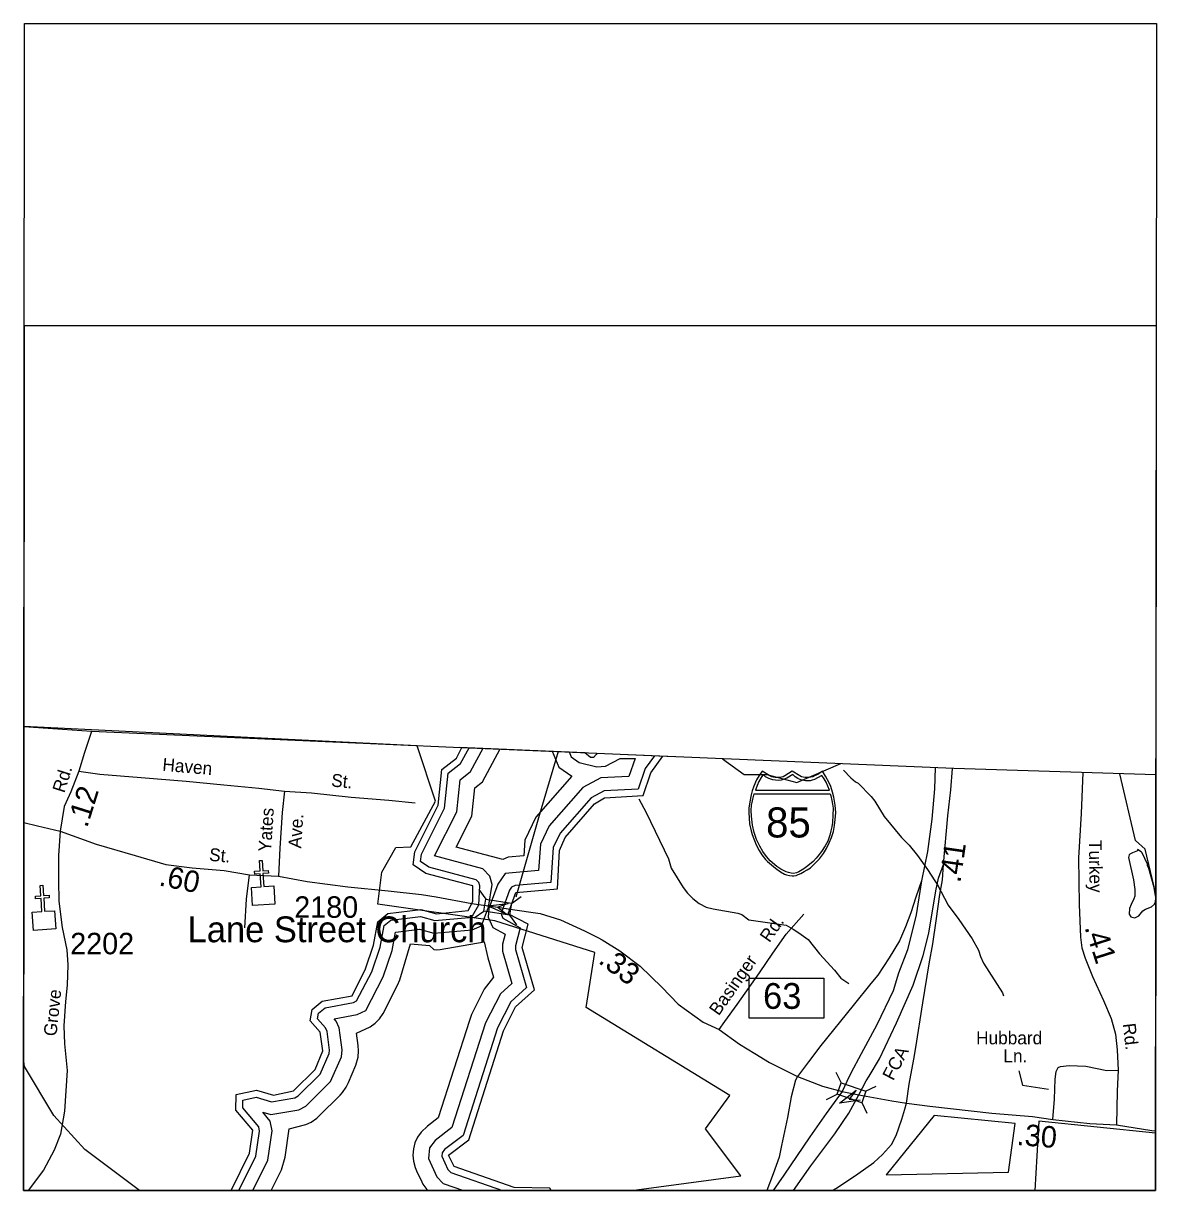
# Model space of a CAD drawing. Extents: x 1513414 to 1532852, y 643392 to 657912.
# Drawn here: x 1513414 to 1520009, y 651120 to 657912 of the extents above; entities that cross this region are included whole.
import ezdxf

# ---------------------------------------------------------------- set-up
doc = ezdxf.new("R2010")
doc.units = 0
doc.layers.add('Default', color=7, linetype='Continuous')

msp = doc.modelspace()

# ---------------------------------------------------------------- linework, layer by layer
at = {"layer": 'Default'}
for p, q in [((1520007.5, 656151.4), (1513418.3, 656151.4)), ((1516681.5, 653667), (1515951, 653698)), ((1517202.2, 653645), (1516751, 653664.1)), ((1516065.3, 652873.3), (1516105.4, 652817.1)), ((1516254.4, 652792), (1516310.5, 652832.1)), ((1516037.6, 652707.4), (1516093.8, 652747.5)), ((1516243, 652723.9), (1516283.1, 652667.8)), ((1518142.8, 651810.5), (1518172.9, 651748.4)), ((1518315.6, 651698.6), (1518377.7, 651728.7)), ((1518087.8, 651651.6), (1518149.8, 651681.7)), ((1518293, 651633.4), (1518323.2, 651571.3))]:
    msp.add_line(p, q, dxfattribs=at)
for points in [[(1513419.9, 657912), (1520009.1, 657912), (1520002.8, 651120.5), (1513413.6, 651120.5)], [(1517888.8, 652951.5), (1517898.3, 652952.5), (1517911.1, 652954.9), (1517923.4, 652959), (1517937.6, 652965.2), (1517958.4, 652976.8), (1517975.1, 652986.6), (1517994.5, 652999.6), (1518020.6, 653023.3), (1518046.6, 653050.7), (1518069.6, 653081.8), (1518087.9, 653110.8), (1518104, 653143.9), (1518117.4, 653174.8), (1518128.1, 653210.2), (1518135.1, 653244.4), (1518138.7, 653280.1), (1518141.1, 653319.7), (1518138.4, 653364.2), (1518130.6, 653409.8), (1518123.4, 653438.1), (1518112.3, 653472.1), (1518103.3, 653493.7), (1518082.5, 653532.2), (1518063.8, 653561.8), (1518036.5, 653542.6), (1518018.8, 653533.2), (1518007.9, 653528.3), (1517996.8, 653526.1), (1517976.3, 653523.6), (1517963.4, 653524.2), (1517951.4, 653526.9), (1517941.3, 653529.1), (1517933.1, 653533.2), (1517888.8, 653561.8), (1517844.6, 653533.2), (1517835.3, 653528.9), (1517825.8, 653526.9), (1517816.6, 653524.4), (1517801.5, 653523.6), (1517789.9, 653524), (1517778.1, 653526.1), (1517768.7, 653528.1), (1517758.2, 653533.2), (1517713, 653561.8), (1517695.3, 653536.1), (1517680.9, 653510.7), (1517665.5, 653474.7), (1517656, 653446.9), (1517649.1, 653424), (1517640.8, 653382.1), (1517636.5, 653345.5), (1517635.7, 653319.7), (1517640.5, 653255.2), (1517647.5, 653220.8), (1517654.7, 653193), (1517678.6, 653133), (1517696.5, 653099.4), (1517712, 653075.2), (1517733.5, 653048), (1517745.2, 653035.1), (1517790, 652995.9), (1517820, 652975.5), (1517843.9, 652962.6), (1517855.1, 652958.3), (1517872.7, 652953.4)], [(1517718.4, 653541), (1517707.4, 653524.1), (1517694.7, 653501.3), (1517684.6, 653477.6), (1517674.2, 653451.4), (1518105.8, 653451.3), (1518095.8, 653473.7), (1518085, 653496.2), (1518073.7, 653516.8), (1518060, 653536.7), (1518035.8, 653521.5), (1518018.2, 653513.1), (1518004, 653508.2), (1517992, 653505.5), (1517973.4, 653504.1), (1517965.1, 653504.6), (1517939.2, 653510.4), (1517921.6, 653517.6), (1517904.9, 653528.7), (1517891.4, 653541.5), (1517857.2, 653520.8), (1517842.1, 653514.1), (1517824.6, 653509.6), (1517805.5, 653507.3), (1517776.1, 653510.4), (1517753, 653518.4), (1517733.2, 653528.7)], [(1518108.4, 653430), (1518113, 653417.8), (1518119.3, 653390.7), (1518122.7, 653369.9), (1518126.1, 653345.9), (1518124.9, 653304.8), (1518122.9, 653262.2), (1518119, 653237), (1518113.8, 653214.1), (1518106.6, 653188.6), (1518095.1, 653154.8), (1518079.2, 653126.1), (1518059.3, 653094.3), (1518037.8, 653066.4), (1518028.5, 653054.9), (1518010.8, 653036.2), (1517978.6, 653010.3), (1517955, 652992.7), (1517926.9, 652976.1), (1517912.6, 652969.7), (1517895.9, 652966.2), (1517882.2, 652967.2), (1517865.6, 652971.6), (1517852.1, 652975.3), (1517822.7, 652991.2), (1517798.8, 653007.1), (1517759.1, 653039.8), (1517737.6, 653064.9), (1517717.6, 653094.3), (1517699.7, 653124.4), (1517680.6, 653164), (1517667.2, 653203.9), (1517657.4, 653247), (1517650.8, 653299.7), (1517650, 653331.7), (1517652, 653362.6), (1517654.9, 653378.7), (1517658.8, 653398.8), (1517666.7, 653429.8)], [(1514740.5, 652884.8), (1514797.3, 652888.7), (1514792.2, 652964.7), (1514760.3, 652962.5), (1514759.3, 652978.5), (1514791.2, 652980.6), (1514787.2, 653040.6), (1514803.2, 653041.7), (1514807.2, 652981.7), (1514839.1, 652983.8), (1514840.2, 652967.9), (1514808.2, 652965.7), (1514813.3, 652889.8), (1514870.8, 652893.5), (1514877.9, 652787.3), (1514747.6, 652778.6)], [(1513464.7, 652740.6), (1513521.5, 652744.5), (1513516.5, 652820.5), (1513484.5, 652818.3), (1513483.5, 652834.3), (1513515.4, 652836.4), (1513511.4, 652896.4), (1513527.4, 652897.5), (1513531.4, 652837.5), (1513563.3, 652839.6), (1513564.4, 652823.7), (1513532.4, 652821.5), (1513537.5, 652745.6), (1513595.1, 652749.3), (1513602.1, 652643.1), (1513471.8, 652634.4)], [(1516105.4, 652817.1), (1516254.5, 652792.3), (1516242.8, 652722.7), (1516093.8, 652747.5)], [(1516226, 652729), (1516114.6, 652778.5), (1516235.8, 652791.3), (1516174.8, 652769)], [(1517637.1, 652356.5), (1518072, 652356.5), (1518072, 652123.3), (1517637.1, 652123.3)], [(1518172.9, 651748.4), (1518315.7, 651698.9), (1518292.6, 651632.2), (1518149.8, 651681.7)], [(1518284.2, 651646.1), (1518163.3, 651630.1), (1518260, 651704.4), (1518219.6, 651653.5)]]:
    msp.add_lwpolyline(points, close=True, dxfattribs=at)
for points in [[(1513418.3, 656151.4), (1513413.6, 651120.5), (1520002.8, 651120.5), (1520007.5, 656151.4)], [(1515706.2, 653709.1), (1513416.1, 653820.9)], [(1515706.2, 653709.1), (1513416.1, 653820.9)], [(1520005, 653539), (1518827.8, 653576.1), (1515916.8, 653699.4), (1513810.1, 653792.1), (1513416.1, 653818.1)], [(1513810.6, 653792.1), (1513769.4, 653670.3), (1513736.4, 653561.3), (1513690.2, 653440.8), (1513650.6, 653354.9), (1513627.8, 653211.3)], [(1515451.4, 652549), (1515476.6, 652685), (1515535.6, 652733), (1515727.6, 652755.4), (1515818.6, 652730.6), (1516002.6, 652749.8), (1516028.6, 652801.9), (1516029.6, 652893.7), (1515755.6, 652964.9), (1515681.6, 653015.7), (1515691.6, 653090.9), (1515828.6, 653363.9), (1515848.6, 653570.3), (1515933.6, 653637.5), (1515965.7, 653699.3)], [(1516951.9, 651120.5), (1517589, 651207.6), (1517383.6, 651479.3), (1517525.8, 651673.5), (1516689.2, 652186.4), (1516739.5, 652507), (1516158.3, 652690.2), (1515476.3, 652786.4), (1515499.2, 652974.2), (1515581.6, 653116.2), (1515668.5, 653120.8), (1515813.1, 653386.6), (1515706.2, 653709.1)], [(1516951.9, 651120.5), (1517589, 651207.6), (1517383.6, 651479.3), (1517525.8, 651673.5), (1516689.2, 652186.4), (1516739.5, 652507), (1516158.3, 652690.2), (1515476.3, 652786.4), (1515499.2, 652974.2), (1515581.6, 653116.2), (1515668.5, 653120.8), (1515813.1, 653386.6), (1515706.2, 653709.1)], [(1515724.5, 653034.8), (1515730.4, 653079), (1515864.4, 653346), (1515886.7, 653549.5), (1515958.4, 653606.1), (1516007.6, 653697.6)], [(1515806.4, 653067.9), (1515935.5, 653325), (1515955.9, 653511.2), (1516015.5, 653558.3), (1516088.7, 653694.4)], [(1515933.3, 653119.7), (1516023.3, 653299), (1516041.4, 653463.8), (1516086.1, 653499.1), (1516188.9, 653690.3)], [(1517086.8, 653650.2), (1517033.2, 653575.7), (1516992.1, 653457.2), (1516794.5, 653446.7), (1516717.3, 653406.3), (1516537.3, 653201.2), (1516497.2, 653116.8), (1516483.5, 652914), (1516276.1, 652895.7), (1516253.9, 652886.5), (1516242, 652869.5), (1516197.9, 652745.4), (1516196.2, 652725.1), (1516204.9, 652706.4), (1516305, 652650), (1516278, 652545.1), (1516278.4, 652524.1), (1516342.2, 652302.1), (1516250.7, 652219.3), (1516172.8, 652067.5), (1515972.3, 651441.3), (1515864.5, 651359.5), (1515850.9, 651341.3), (1515849.2, 651320.7), (1515884.6, 651243.9), (1515900.5, 651226.7), (1516202.7, 651120.5)], [(1516973.7, 653635.3), (1516937.3, 653530), (1516774, 653521.4), (1516669.7, 653466.7), (1516473.5, 653243.2), (1516422.7, 653136.3), (1516412.4, 652983.7), (1516217.5, 652966.5)], [(1516316.8, 652535.1), (1516351.6, 652670.6), (1516235.6, 652732), (1516279.6, 652855.8), (1516521.5, 652877.2), (1516533.6, 653100.3), (1516567.6, 653175.1), (1516737.6, 653371.8), (1516796.6, 653406.8), (1517021.6, 653418.7), (1517065.7, 653552.3), (1517134.6, 653647.9)], [(1516280.9, 652830.5), (1516413, 653292.1), (1516528, 653676.6)], [(1516280.9, 652830.5), (1516413, 653292.1), (1516528, 653676.6)], [(1516491.3, 653677.6), (1516529.5, 653585.1), (1516605.1, 653532.5)], [(1516590.6, 653673.4), (1516602.7, 653644), (1516648.5, 653612.1), (1516751.7, 653587.1), (1516800.6, 653589.9), (1516887.8, 653633.9), (1516973.7, 653635.3)], [(1516751, 653664.1), (1516747, 653657.2), (1516730.9, 653641.1), (1516714.9, 653639.8), (1516681.5, 653667)], [(1516751, 653664.1), (1516747, 653657.2), (1516730.9, 653641.1), (1516714.9, 653639.8), (1516681.5, 653667)], [(1517483, 653631.9), (1517607.6, 653541.4), (1517740.6, 653542), (1517914.6, 653495.8), (1518170.7, 653606.5)], [(1513736.4, 653561.3), (1513859.7, 653543.2), (1514099.3, 653525), (1514360.9, 653502.1), (1514580.4, 653482.2), (1514784.1, 653462.5), (1514933.9, 653445.7)], [(1518186.2, 653566.7), (1518229.5, 653521.4), (1518257.2, 653499.6), (1518271.1, 653491.1), (1518348, 653414), (1518369.4, 653385.7), (1518424, 653296.8), (1518524.1, 653175), (1518569.6, 653129.7), (1518616.6, 653069.7), (1518675.2, 652988.1), (1518718.3, 652924), (1518734, 652899.1), (1518796.2, 652782.1), (1518856.9, 652697.2), (1518935.1, 652586.5), (1518972.1, 652519.3), (1518983.4, 652483)], [(1518720.9, 653580.6), (1518716.2, 653458.2), (1518700.6, 653282.5), (1518674.7, 653094.2), (1518639.9, 652923.6)], [(1518767.9, 653018.5), (1518794.2, 653301.7), (1518811.4, 653453.3), (1518821.6, 653576.3)], [(1516605.1, 653532.5), (1516396, 653294.2), (1516332.2, 653160), (1516326, 653068.4), (1516235.7, 653060.4), (1516204.9, 653047.7)], [(1519578.6, 653552.4), (1519568.8, 653314.9), (1519554, 653056.2), (1519559, 652786.1), (1519565.3, 652596.1), (1519574.3, 652533.9), (1519593.4, 652473.6), (1519636.1, 652366.4), (1519700, 652227.4), (1519744.3, 652122.7), (1519768.8, 652030.1), (1519779.4, 651940.1), (1519785.6, 651821.9), (1519779.2, 651699.1), (1519774.5, 651504)], [(1520004.4, 652847.5), (1519942.6, 653107), (1519885.6, 653157.4), (1519794.8, 653545.6)], [(1514933.9, 653445.7), (1514919.5, 653320.1), (1514905.9, 653112.3), (1514899.1, 652950.4)], [(1514933.9, 653445.7), (1515089.7, 653434.9), (1515321.2, 653410.7), (1515540.9, 653392.6), (1515694.6, 653375.9)], [(1516995.2, 653401.1), (1517037.9, 653320.6), (1517167.7, 653050.5), (1517182.9, 652997.7), (1517253.1, 652884.7), (1517278.7, 652852.2), (1517310.1, 652819.5), (1517347.6, 652790.8), (1517387.5, 652770.3), (1517427.3, 652759.7), (1517571, 652735.5), (1517594.8, 652727.6), (1517636.2, 652696.4), (1517853.9, 652664.9), (1517893.7, 652642.8), (1517927.3, 652619.9), (1517980.6, 652581.1), (1518047.4, 652497.7)], [(1513415.6, 653263), (1513496.3, 653244), (1513627.8, 653211.3)], [(1513627.8, 653211.3), (1513618.1, 653070.9), (1513618.1, 652925.3), (1513619.4, 652804.4), (1513638.9, 652652.3), (1513666.1, 652520.8), (1513673, 652434.6), (1513668.7, 652316), (1513659, 652221), (1513649.2, 652078.6), (1513653.1, 651975.3), (1513668.7, 651819.3), (1513653.3, 651583.9), (1513629.1, 651448.2), (1513592.6, 651356.2), (1513530.8, 651239.1), (1513441.7, 651120.5)], [(1513627.8, 653211.3), (1513838.4, 653135.6), (1514064.2, 653069.6), (1514243.3, 653018.4), (1514396, 652999.5), (1514581.6, 652982.2), (1514729.1, 652957.6), (1514899.1, 652950.4), (1515064.5, 652919.4), (1515302, 652887.2), (1515537.4, 652864.8), (1515731.1, 652843.3), (1515816.9, 652829.8), (1516024.2, 652792), (1516174.8, 652769)], [(1516204.9, 653047.7), (1515933.3, 653119.7)], [(1519897.6, 653105.4), (1519897.5, 653097.2), (1519869.3, 653085.5), (1519853.1, 653077.6), (1519849.2, 653073.6), (1519845, 653058.1), (1519874.8, 652929.5), (1519882, 652873.5), (1519881.3, 652833.3), (1519877, 652817.8), (1519860.6, 652785.3), (1519850.3, 652761.7), (1519849.6, 652729.7), (1519859.4, 652714), (1519881.4, 652706.9), (1519905.6, 652718.7), (1519928, 652748.7), (1519944.2, 652758.2), (1519978.5, 652771.4), (1519996.7, 652787.5), (1520002.8, 652797.2), (1520003.4, 652827.5), (1520001.4, 652835.8), (1519994.1, 652883.5), (1519964, 652995.7), (1519956.3, 653012.3), (1519956.5, 653020.5), (1519925.3, 653085.1), (1519919.6, 653092.7), (1519897.6, 653105.4)], [(1514668.3, 651120.5), (1514766.4, 651320.2), (1514788.2, 651466.7), (1514783.2, 651492), (1514690.9, 651603.1), (1514691.9, 651647.9), (1514767.9, 651663.5), (1514857.6, 651637.9), (1514993.6, 651661.1), (1515013.7, 651671.8), (1515140.7, 651797.3), (1515193.6, 651918), (1515196.2, 651938.7), (1515181.2, 652047.3), (1515172.2, 652067.5), (1515126, 652120.9), (1515130.8, 652152.8), (1515169.9, 652184.7), (1515334.9, 652215.4), (1515353.4, 652224.1), (1515441.3, 652392.8), (1515489.3, 652536.5), (1515513.2, 652663.2), (1515551.9, 652694.7), (1515724.6, 652714.8), (1515808.1, 652692.1), (1516006.8, 652710.1), (1516028.3, 652719.2), (1516064.4, 652784), (1516069.6, 652893.3), (1516064.2, 652913.7), (1516049.6, 652928.4), (1515772.5, 653001.8), (1515724.5, 653034.8)], [(1516087.2, 652993.4), (1515806.4, 653067.9)], [(1518276, 651678.5), (1518319.5, 651760.3), (1518335.4, 651786.9), (1518396.9, 651887.5), (1518496, 652096.2), (1518591.1, 652316.2), (1518649.5, 652488.5), (1518682.4, 652617.7), (1518723.7, 652864.5), (1518739.2, 652938), (1518767.9, 653018.5)], [(1518553.2, 651630.2), (1518569.6, 651740.9), (1518595.4, 651885.3), (1518607.7, 651953.3), (1518648.5, 652213.7), (1518685.2, 652439.8), (1518707, 652556.3), (1518726.1, 652689.6), (1518747.8, 652843.5), (1518762.8, 652928.8), (1518767.9, 653018.5)], [(1514701.7, 652650), (1514712.7, 652815.8), (1514729.1, 652957.6)], [(1514749.1, 651120.5), (1514836.5, 651298.4), (1514861.8, 651468.5), (1514850.8, 651524.2), (1514806.9, 651577), (1514853.5, 651563.7), (1515017.4, 651591.5), (1515057.2, 651612.9), (1515201.6, 651755.5), (1515264.3, 651898.6), (1515269.3, 651939.2), (1515251.7, 652067.5), (1515234, 652106.9), (1515222.1, 652120.7), (1515357.3, 652145.8), (1515406.3, 652168.8), (1515508.3, 652364.4), (1515559.7, 652518.2), (1515579.6, 652623.7), (1515581.2, 652625.1), (1515719.1, 652641.1), (1515801.6, 652618.7), (1516024.7, 652638.9), (1516079.6, 652662.2), (1516120.2, 652769.2), (1516142.6, 652901.1), (1516129.3, 652951.1), (1516087.2, 652993.4)], [(1516217.5, 652966.5), (1516174.1, 652904.5), (1516123.3, 652761.4), (1516119.2, 652711.3), (1516146.6, 652652.4), (1516217.3, 652612.6), (1516202.3, 652554.1), (1516202.9, 652512.9), (1516256.5, 652326.5), (1516189.7, 652266.2), (1516102.6, 652096.5), (1515907.6, 651487.2), (1515810.2, 651413.2), (1515777.4, 651369.1), (1515772.1, 651307.2), (1515820.9, 651201.3), (1515857.8, 651161.5), (1515974.6, 651120.5)], [(1518639.9, 652923.6), (1518606.9, 652828.7), (1518578.3, 652737.4), (1518547, 652655.7), (1518511.6, 652574), (1518451.7, 652474.6), (1518387.1, 652374.7), (1518346.3, 652325.6), (1518242.8, 652197.6), (1518055, 651964.4), (1517982.9, 651870.4), (1517919.7, 651785.6)], [(1518639.9, 652923.6), (1518610, 652725.2), (1518558.6, 652522.5), (1518506.6, 652386.6), (1518475.7, 652282.6), (1518380.3, 652085.4), (1518289.6, 651916.4), (1518230.2, 651803.4), (1518206.3, 651755.1), (1518179.8, 651697.8)], [(1516174.8, 652769), (1516247.6, 652757.9), (1516421, 652732.8), (1516540.5, 652696.5), (1516679.3, 652632.1), (1516756.7, 652593.1), (1516782.3, 652580.2), (1516885.2, 652515.7), (1517003.9, 652425.9), (1517130.1, 652303.9), (1517224.6, 652206.3), (1517370.9, 652099.9), (1517462.7, 652058), (1517580.9, 651972.7), (1517671.5, 651917.8), (1517756.7, 651865.5), (1517919.7, 651785.6)], [(1517462.7, 652058), (1517497, 652104), (1517568.7, 652203), (1517697.6, 652386.9), (1517775, 652501.7), (1517852.9, 652612.8), (1517954.9, 652728.8)], [(1514623.8, 651120.5), (1514730.6, 651337.8), (1514748.6, 651472), (1514650.6, 651588.9), (1514652.6, 651680.7), (1514769.6, 651704.6), (1514868.6, 651676.4), (1514985.6, 651700.3), (1515112.5, 651825.8), (1515156.6, 651933.2), (1515141.5, 652041.8), (1515083.6, 652108.6), (1515093.6, 652174.1), (1515152.6, 652222.1), (1515327.6, 652254.7), (1515405.6, 652410.7), (1515451.4, 652549)], [(1514855.8, 651120.5), (1514915.1, 651240.8), (1514938, 651315.9), (1514960, 651479.6), (1515057.1, 651504.7), (1515089.6, 651519.9), (1515120.8, 651541.8), (1515133.1, 651553), (1515257.9, 651676.3), (1515271.4, 651690.8), (1515293.3, 651722.2), (1515306.4, 651749), (1515348.1, 651850.6), (1515361.7, 651897.8), (1515364.9, 651933.9), (1515362.8, 651964.1), (1515352.5, 652037.6), (1515431.7, 652074.4), (1515461.4, 652095.2), (1515487.1, 652120.8), (1515508.5, 652151.5), (1515590.9, 652315.3), (1515604.1, 652346.8), (1515666.7, 652556.1), (1515778, 652547.6), (1515802, 652523.9), (1515819.9, 652522.3), (1515839.6, 652523.3), (1516095.7, 652568.9)], [(1516095.7, 652568.9), (1516116.9, 652475.7), (1516149.4, 652363.4), (1516096.2, 652292), (1516022.7, 652144.5), (1516009.2, 652110.8), (1515828.1, 651543.3), (1515765.7, 651496.1), (1515728.6, 651460.7), (1515708.3, 651431.7), (1515692.9, 651398.8), (1515683.5, 651363.7), (1515680.3, 651327.6), (1515683.5, 651291.4), (1515693.3, 651255.1), (1515701.6, 651235.4), (1515732.3, 651171.8), (1515739.2, 651158.6), (1515761, 651127.4), (1515768, 651120.5)], [(1516486.1, 651120.5), (1516477.6, 651135.2), (1516269.5, 651139.4), (1515920.5, 651261.3), (1515888.6, 651327.6), (1516006.6, 651417.1), (1516208.5, 652049.8), (1516277.6, 652189.6), (1516387.5, 652289.1), (1516316.8, 652535.1)], [(1518047.4, 652497.7), (1518134.2, 652402.4), (1518171.6, 652357.4), (1518217.1, 652325.3)], [(1518983.4, 652483), (1519000.8, 652444.8), (1519112.5, 652271.1), (1519118.3, 652254.6)], [(1514088.8, 651120.5), (1513771.6, 651360.5), (1513591.6, 651557.8), (1513420.5, 651843.5), (1513414.3, 651888.1)], [(1519206.5, 651816.7), (1519229.2, 651734.7), (1519379.6, 651711.9)], [(1519405.7, 651534.6), (1519414.7, 651653.7), (1519418.6, 651769.7), (1519423.3, 651813.6), (1519435.6, 651837.3), (1519449.7, 651843.1), (1519499.8, 651848.5), (1519597.8, 651844.9), (1519719.5, 651818.8), (1519785.6, 651821.9)], [(1517919.7, 651785.6), (1517906.7, 651764.2), (1517882.2, 651666.1), (1517860.4, 651546.3), (1517826.4, 651383.9), (1517811.4, 651315.8), (1517777.4, 651219.1), (1517740, 651120.5)], [(1517919.7, 651785.6), (1518063.7, 651728.4), (1518179.8, 651697.8)], [(1518179.8, 651697.8), (1518086.4, 651568.6), (1517990.2, 651433.8), (1517839.1, 651211.1), (1517777.3, 651120.5)], [(1517895.3, 651120.5), (1517996.4, 651265.3), (1518135.9, 651450.3), (1518218.3, 651571.3), (1518276, 651678.5)], [(1518179.8, 651697.8), (1518276, 651678.5)], [(1518276, 651678.5), (1518468.3, 651642.8), (1518553.2, 651630.2)], [(1518121.6, 651120.5), (1518145.5, 651135.6), (1518269.4, 651218.7), (1518363.3, 651284), (1518413.6, 651330.3), (1518465.3, 651388.9), (1518492.5, 651440.6), (1518526, 651536.7), (1518543.7, 651595.2), (1518553.2, 651630.2)], [(1518553.2, 651630.2), (1518689.5, 651612.6), (1519050.7, 651571.3), (1519286, 651551), (1519405.7, 651534.6), (1519619.5, 651511.1), (1519774.5, 651504)], [(1518714.1, 651556.8), (1518434.8, 651212.3), (1519147.7, 651227.6), (1519184.8, 651511.9), (1518714.1, 651556.8)], [(1518714.1, 651556.8), (1518434.8, 651212.3), (1519147.7, 651227.6), (1519184.8, 651511.9), (1518714.1, 651556.8)], [(1518714.1, 651556.8), (1518434.8, 651212.3), (1519147.7, 651227.6), (1519184.8, 651511.9), (1518714.1, 651556.8)], [(1518714.1, 651556.8), (1518434.8, 651212.3), (1519147.7, 651227.6), (1519184.8, 651511.9), (1518714.1, 651556.8)], [(1520003.1, 651455.2), (1519323.3, 651524.8), (1519300.5, 651120.5)], [(1520003.1, 651455.2), (1519323.3, 651524.8), (1519300.5, 651120.5)], [(1520003.1, 651455.2), (1519323.3, 651524.8), (1519300.5, 651120.5)], [(1520003.1, 651455.2), (1519323.3, 651524.8), (1519300.5, 651120.5)], [(1519300.5, 651120.5), (1520002.8, 651120.5), (1520003.1, 651455.2)], [(1519300.5, 651120.5), (1520002.8, 651120.5), (1520003.1, 651455.2)], [(1519300.5, 651120.5), (1520002.8, 651120.5), (1520003.1, 651455.2)], [(1519300.5, 651120.5), (1520002.8, 651120.5), (1520003.1, 651455.2)], [(1519774.5, 651504), (1519981.1, 651471.1), (1520003.1, 651469.2)]]:
    msp.add_lwpolyline(points, dxfattribs=at)

# ---------------------------------------------------------------- texts
for s, height, rotation, p in [('Haven', 75, 354.83638, (1514220.7, 653564.2)), ('Rd.', 75, 72.50344, (1513652.4, 653430.5)), ('St.', 75, 354.01104, (1515202.7, 653472.6)), ('.12', 125, 72.50344, (1513784.7, 653227.3)), ('Yates', 75, 86.25533, (1514855.1, 653089.6)), ('Ave.', 75, 86.25533, (1515030.3, 653110.4)), ('Turkey', 75, 271.05034, (1519613.9, 653160.4)), ('St.', 75, 354.65808, (1514492.4, 653039.9)), ('.41', 125, 81.76303, (1518866.6, 652907.8)), ('.60', 125, 348.20453, (1514198, 652897.5)), ('Rd.', 75, 54.96632, (1517755.4, 652559.5)), ('.41', 125, 287.59839, (1519588.3, 652652.6)), ('.33', 125, 322.66307, (1516754.3, 652449.5)), ('Basinger', 75, 54.95724, (1517460.3, 652134.1)), ('Grove', 75, 83.90792, (1513606, 652016.4)), ('Rd.', 75, 276.70717, (1519811.2, 652090.7)), ('FCA', 75, 62.56082, (1518475.9, 651756.3)), ('.30', 125, 355.24857, (1519191.7, 651386.8))]:
    msp.add_text(s, height=height, rotation=rotation, dxfattribs=at).set_placement(p)
for s, height, p in [('85', 175, (1517736, 653175.3)), ('2180', 125, (1514990.3, 652708)), ('Lane Street Church', 150, (1514369.6, 652565.8)), ('2202', 125, (1513686.5, 652495.7)), ('63', 150, (1517718.5, 652178.2)), ('Hubbard', 75, (1518958.3, 651971.8)), ('Ln.', 75, (1519117.2, 651867))]:
    msp.add_text(s, height=height, dxfattribs=at).set_placement(p)

doc.saveas('drawing.dxf')
